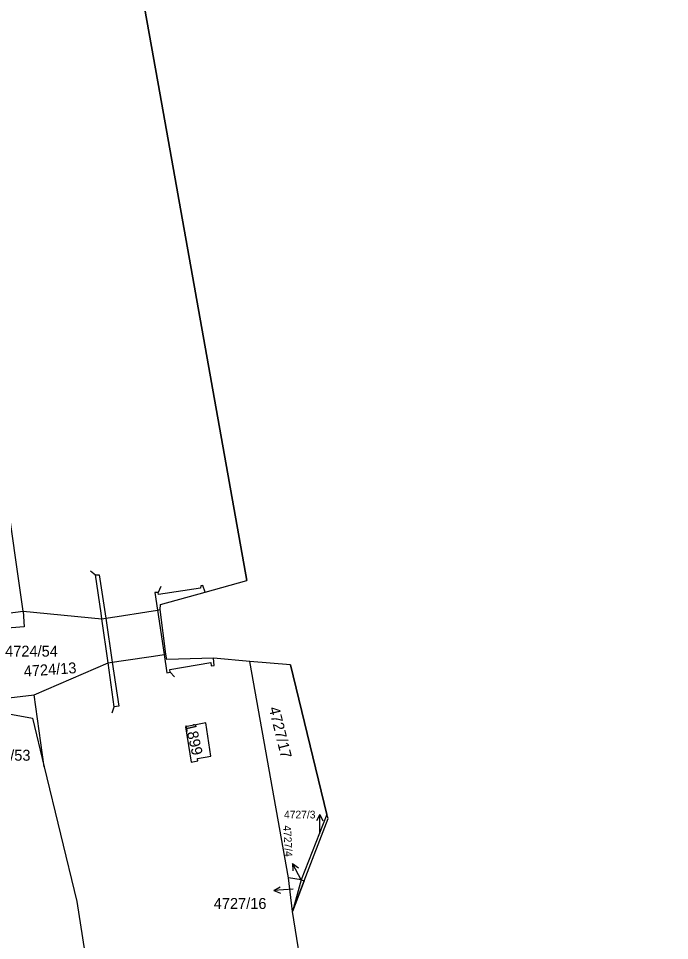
# Model space of a CAD drawing. Extents: x -756746 to -753363, y -1166406 to -1161727.
# Drawn here: x -755037.3 to -754935.8, y -1164967.1 to -1164823.5 of the extents above; entities that cross this region are included whole.
import ezdxf

# ---------------------------------------------------------------- set-up
doc = ezdxf.new("R2010")
doc.units = 0
for name, color, linetype in [('Hranice kat_území', 7, 'Continuous'), ('Hranice parcel', 7, 'Continuous'), ('Parcelní čísla', 7, 'Continuous'), ('Pop  PČ popisy', 7, 'Continuous'), ('Vnitřní kresba', 7, 'Continuous')]:
    doc.layers.add(name, color=color, linetype=linetype)

msp = doc.modelspace()

# ---------------------------------------------------------------- linework, layer by layer
at = {"layer": 'Hranice kat_území'}
for points in [[(-755001.22, -1164923.65), (-755006.88, -1164923.14), (-755014.16, -1164923.37), (-755014.29, -1164922.54), (-755015.21, -1164915.59), (-755015.13, -1164914.81), (-755008.18, -1164912.85), (-755001.66, -1164911.05), (-755015.17, -1164835.37), (-755025.94, -1164775.39)], [(-754935.8, -1165289.03), (-754949.37, -1165208.56), (-754957, -1165164.49), (-754959.9, -1165147.7), (-754966.3, -1165104.74), (-754968.36, -1165093.02), (-754976.24, -1165048.43), (-754987.93, -1165004.14), (-754985.68, -1165003.01), (-754990.93, -1164985.27), (-754994.58, -1164962.6), (-754992.74, -1164957.82), (-754989.03, -1164948.14), (-754989.19, -1164947.5), (-754994.89, -1164924.18), (-755001.22, -1164923.65)]]:
    msp.add_lwpolyline(points, dxfattribs=at)
at = {"layer": 'Hranice parcel'}
for p, q in [((-755036.55, -1164915.83), (-755039.34, -1164896.17)), ((-755048.4, -1164917.29), (-755036.55, -1164915.83)), ((-755014.29, -1164922.54), (-755015.21, -1164915.59)), ((-754995.17, -1164957.39), (-755001.22, -1164923.65)), ((-754994.89, -1164924.18), (-755001.22, -1164923.65)), ((-754994.89, -1164924.18), (-754989.19, -1164947.5)), ((-755044.78, -1164930.05), (-755034.81, -1164928.87)), ((-755033.26, -1164940.08), (-755034.81, -1164928.87)), ((-754989.19, -1164947.5), (-754993.2, -1164957.71)), ((-754994.58, -1164962.6), (-754995.17, -1164957.39)), ((-754993.2, -1164957.71), (-754995.17, -1164957.39)), ((-754993.2, -1164957.71), (-754994.58, -1164962.6)), ((-754992.74, -1164957.82), (-754994.58, -1164962.6)), ((-754993.2, -1164957.71), (-754992.74, -1164957.82))]:
    msp.add_line(p, q, dxfattribs=at)
for points in [[(-755026.35, -1164772.59), (-755025.94, -1164775.39), (-755015.17, -1164835.37), (-755001.66, -1164911.05)], [(-755015.21, -1164915.59), (-755015.13, -1164914.81), (-755008.18, -1164912.85), (-755001.66, -1164911.05)], [(-755036.55, -1164915.83), (-755036.41, -1164918.26), (-755048.2, -1164919.19)], [(-755036.55, -1164915.83), (-755024.3, -1164917.04), (-755023.67, -1164916.94), (-755021.9, -1164916.66), (-755017.29, -1164915.93), (-755015.62, -1164915.66), (-755015.21, -1164915.59)], [(-755034.81, -1164928.87), (-755023.27, -1164923.86), (-755022.65, -1164923.77), (-755020.91, -1164923.52), (-755016.24, -1164922.83), (-755014.57, -1164922.59), (-755014.29, -1164922.54)], [(-755001.22, -1164923.65), (-755006.88, -1164923.14), (-755014.16, -1164923.37), (-755014.29, -1164922.54)], [(-755044.55, -1164930.79), (-755035.08, -1164932.5), (-755033.26, -1164940.08)], [(-755009.31, -1164939.13), (-755009.37, -1164938.81), (-755007.31, -1164938.4), (-755008.06, -1164933.24), (-755011.24, -1164933.84), (-755010.38, -1164939.36), (-755009.31, -1164939.13)], [(-755033.26, -1164940.08), (-755028.2, -1164961.07), (-755024.41, -1164985.35), (-755021.39, -1165008.96), (-755002.65, -1165161.79), (-754999.85, -1165183.96)], [(-754992.74, -1164957.82), (-754989.03, -1164948.14), (-754989.19, -1164947.5)], [(-754987.93, -1165004.14), (-754985.68, -1165003.01), (-754990.93, -1164985.27), (-754994.58, -1164962.6)]]:
    msp.add_lwpolyline(points, dxfattribs=at)
at = {"layer": 'Pop  PČ popisy'}
for p, q in [((-754990.32, -1164947.52), (-754990.82, -1164948.52)), ((-754990.32, -1164950.52), (-754990.32, -1164947.52)), ((-754990.32, -1164947.52), (-754989.82, -1164948.52)), ((-754993.14, -1164957.81), (-754994.55, -1164955.16)), ((-754994.55, -1164955.16), (-754993.64, -1164955.81)), ((-754994.55, -1164955.16), (-754994.52, -1164956.28)), ((-754997.45, -1164959.35), (-754996.49, -1164958.78)), ((-754994.46, -1164959.14), (-754997.45, -1164959.35)), ((-754997.45, -1164959.35), (-754996.42, -1164959.78))]:
    msp.add_line(p, q, dxfattribs=at)
at = {"layer": 'Vnitřní kresba'}
for p, q in [((-755026.04, -1164909.57), (-755025.25, -1164910.19)), ((-755025.25, -1164910.19), (-755024.68, -1164910.17)), ((-755024.36, -1164916.13), (-755025.25, -1164910.19)), ((-755024.68, -1164910.17), (-755023.67, -1164916.94)), ((-755015.49, -1164912.9), (-755016.04, -1164912.93)), ((-755016.04, -1164912.93), (-755015.62, -1164915.66)), ((-755015.1, -1164911.98), (-755015.49, -1164912.9)), ((-755015.44, -1164913.25), (-755015.49, -1164912.9)), ((-755008.89, -1164912.25), (-755015.44, -1164913.25)), ((-755008.84, -1164911.9), (-755008.89, -1164912.25)), ((-755008.52, -1164911.81), (-755008.84, -1164911.9)), ((-755008.18, -1164912.85), (-755008.52, -1164911.81)), ((-755015.62, -1164915.66), (-755014.57, -1164922.59)), ((-755024.3, -1164917.04), (-755024.36, -1164916.13)), ((-755023.27, -1164923.86), (-755024.3, -1164917.04)), ((-755023.67, -1164916.94), (-755022.65, -1164923.77)), ((-755014.57, -1164922.59), (-755014.13, -1164925.43)), ((-755022.36, -1164930.71), (-755023.27, -1164923.86)), ((-755022.65, -1164923.77), (-755021.63, -1164930.61)), ((-755013.69, -1164924.94), (-755007.27, -1164923.85)), ((-755007.27, -1164923.85), (-755007.25, -1164924.36)), ((-755007.25, -1164924.36), (-755006.77, -1164924.3)), ((-755006.77, -1164924.3), (-755006.88, -1164923.14)), ((-755014.13, -1164925.43), (-755013.64, -1164925.31)), ((-755013.64, -1164925.31), (-755013.69, -1164924.94)), ((-755012.96, -1164926.04), (-755013.64, -1164925.31)), ((-755022.65, -1164931.67), (-755022.36, -1164930.71)), ((-755021.63, -1164930.61), (-755022.36, -1164930.71))]:
    msp.add_line(p, q, dxfattribs=at)

# ---------------------------------------------------------------- texts
at = {"layer": 'Parcelní čísla'}
for s, height, p in [('4724/54', 1.7, (-755039.35, -1164922.91)), ('4724/53', 1.7, (-755043.62, -1164939.13)), ('4727/3', 1.2, (-754995.89, -1164948.12)), ('4727/16', 1.7, (-755006.84, -1164962.22))]:
    msp.add_text(s, height=height, dxfattribs=at).set_placement(p)
for s, height, rotation, p in [('4724/13', 1.7, 4, (-755036.39, -1164926.05)), ('4727/17', 1.7, 284, (-754998.28, -1164930.94)), ('1899', 1.7, 283, (-755011.31, -1164933.49)), ('4727/4', 1.2, 273, (-754996.01, -1164949.23))]:
    msp.add_text(s, height=height, rotation=rotation, dxfattribs=at).set_placement(p)

doc.saveas('drawing.dxf')
